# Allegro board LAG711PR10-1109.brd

Outline 228.4 x 155.5 mm; copper layers: TOP, GND1, IN1, VCC, IN2, IN3, GND2, BOTTOM. Coordinates in mm from the lower left corner of the outline.

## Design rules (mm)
net group CB: nets CBN CBP
net group CLK_CNV_CTX_DRX_: nets CLK_CNV_CTX_DRX_N CLK_CNV_CTX_DRX_P
net group CLK_PCIE_2: nets CLK_PCIE_N2 CLK_PCIE_P2
net group CLK_PEG_0: nets CLK_PEG_N0 CLK_PEG_P0
net group CNV_CRX_DTX_0: nets CNV_CRX_DTX_N0 CNV_CRX_DTX_P0
net group CNV_CTX_DRX_0: nets CNV_CTX_DRX_N0 CNV_CTX_DRX_P0
net group CPU_DP1_1: nets CPU_DP1_N1 CPU_DP1_P1
net group CPU_DP1_3: nets CPU_DP1_N3 CPU_DP1_P3
net group DDR_RESET: nets DDR_DRAMRST# DDR_DRAMRST#_R
net group DIFFPAIR12: nets ICSP_CLK ICSP_DAT
net group DIFFPAIR15: nets NCT7718_DXN NCT7718_DXP
net group EDP_AUX: nets EDP_AUXN EDP_AUXP
net group EDP_TX0: nets EDP_TXN0 EDP_TXP0
net group EDP_TX1: nets EDP_TXN1 EDP_TXP1
net group HDMI_L_CLK: nets HDMI_L_CLKN HDMI_L_CLKP
net group HDMI_L_TX_1: nets HDMI_L_TX_N1 HDMI_L_TX_P1
net group HDMI_TX_0: nets HDMI_TX_N0 HDMI_TX_P0
net group HDMI_TX_2: nets HDMI_TX_N2 HDMI_TX_P2
net group LAN_MDI0: nets LAN_MDIN0 LAN_MDIP0
net group LAN_MDI2: nets LAN_MDIN2 LAN_MDIP2
net group M_CLKA1: nets M_CLKA1 M_CLKA#1
net group M_WCKA#1: nets M_WCKA0_0 M_WCKA#0_0
net group M_WCKA#2: nets M_WCKA1_0 M_WCKA#1_0
net group PCIE_CRX_DTX_10: nets PCIE_CRX_DTX_N10 PCIE_CRX_DTX_P10
net group PCIE_CRX_DTX_14: nets PCIE_CRX_DTX_N14 PCIE_CRX_DTX_P14
net group PCIE_CRX_DTX_16: nets PCIE_CRX_DTX_N16 PCIE_CRX_DTX_P16
net group PCIE_CTX_C_DRX_10: nets PCIE_CTX_C_DRX_N10 PCIE_CTX_C_DRX_P10
net group PCIE_CTX_C_DRX_14: nets PCIE_CTX_C_DRX_N14 PCIE_CTX_C_DRX_P14
net group PCIE_CTX_C_DRX_16: nets PCIE_CTX_C_DRX_N16 PCIE_CTX_C_DRX_P16
net group PCIE_CTX_DRX_10: nets PCIE_CTX_DRX_N10 PCIE_CTX_DRX_P10
net group PCIE_CTX_DRX_14: nets PCIE_CTX_DRX_N14 PCIE_CTX_DRX_P14
net group PCIE_CTX_DRX_16: nets PCIE_CTX_DRX_N16 PCIE_CTX_DRX_P16
net group PCIE_RCOMP: nets PCIE_RCOMPN PCIE_RCOMPP
net group PEG_CRX_C_GTX_6: nets PEG_CRX_C_GTX_N6 PEG_CRX_C_GTX_P6
net group PEG_CRX_C_GTX_8: nets PEG_CRX_C_GTX_N8 PEG_CRX_C_GTX_P8
net group PEG_CRX_GTX_6: nets PEG_CRX_GTX_N6 PEG_CRX_GTX_P6
net group PEG_CRX_GTX_8: nets PEG_CRX_GTX_N8 PEG_CRX_GTX_P8
net group PEG_CTX_C_GRX_5: nets PEG_CTX_C_GRX_N5 PEG_CTX_C_GRX_P5
net group PEG_CTX_C_GRX_6: nets PEG_CTX_C_GRX_N6 PEG_CTX_C_GRX_P6
net group PEG_CTX_C_GRX_7: nets PEG_CTX_C_GRX_N7 PEG_CTX_C_GRX_P7
net group PEG_CTX_C_GRX_8: nets PEG_CTX_C_GRX_N8 PEG_CTX_C_GRX_P8
net group PEG_CTX_GRX_6: nets PEG_CTX_GRX_N6 PEG_CTX_GRX_P6
net group PEG_CTX_GRX_8: nets PEG_CTX_GRX_N8 PEG_CTX_GRX_P8
net group RJ45_MDI1: nets RJ45_MDIN1 RJ45_MDIP1
net group RJ45_MDI3: nets RJ45_MDIN3 RJ45_MDIP3
net group SATA_CRX_C_DTX_0: nets SATA_CRX_C_DTX_N0 SATA_CRX_C_DTX_P0
net group SATA_CRX_DTX_0: nets SATA_CRX_DTX_N0 SATA_CRX_DTX_P0
net group SATA_CTX_C_DRX_0: nets SATA_CTX_C_DRX_N0 SATA_CTX_C_DRX_P0
net group SATA_CTX_DRX_0: nets SATA_CTX_DRX_N0 SATA_CTX_DRX_P0
net group USB3_1_MRX_DTX_4: nets USB3_1_MRX_DTX_N4 USB3_1_MRX_DTX_P4
net group USB3_1_MTX_DRX_4: nets USB3_1_MTX_DRX_N4 USB3_1_MTX_DRX_P4
net group USB3_2_MTX_C_DRX_4: nets USB3_2_MTX_C_DRX_N4 USB3_2_MTX_C_DRX_P4
net group USB3_CRX_C_MTX_4: nets USB3_CRX_C_MTX_N4 USB3_CRX_C_MTX_P4
net group USB3_CRX_L_DTX_1: nets USB3_CRX_L_DTX_N1 USB3_CRX_L_DTX_P1
net group USB3_CTX_C_DRX_1: nets USB3_CTX_C_DRX_N1 USB3_CTX_C_DRX_P1
net group USB3_CTX_C_MRX_4: nets USB3_CTX_C_MRX_N4 USB3_CTX_C_MRX_P4
net group USB3_CTX_L_DRX_1: nets USB3_CTX_L_DRX_N1 USB3_CTX_L_DRX_P1
net group USB20_1_R: nets USB20_N1_R USB20_P1_R
net group USB20_2_R: nets USB20_N2_R USB20_P2_R
net group USB20_3_R: nets USB20_N3_R USB20_P3_R
net group USB20_4_R: nets USB20_N4_R USB20_P4_R
net group USB20_4_RR: nets USB20_N4_RR USB20_P4_RR
net group USB20_6: nets USB20_N6 USB20_P6
net group USB20_7: nets USB20_N7 USB20_P7
net group USB20_8: nets USB20_N8 USB20_P8
net group VRAM_ABI: nets M_ABIA0 M_ABIA1
net group VRAM_CLK: nets M_CLKA0 M_CLKA#0
net group 15: nets CLK_TP_SIO XTALIN XTALOUT
net group 20: nets LANXIN LANXIN_R LANXOUT LANXOUT_R XCLK_BIASREF XTAL24_IN XTAL24_IN_R XTAL24_OUT XTAL24_OUT_R
net group ASYNCHRONOUS: nets CATERR# H_PECI H_PROCHOT# H_PROCHOT#_R H_THERMTRIP# H_VCCST_PWRGD PECI_EC SCLK_CPU SDIO_CPU VCCST_PWRGD XDP_BPM#0 XDP_BPM#1 XDP_BPM#2 XDP_BPM#3
net group AUDIO: nets AUD_HP1_JACK_L AUD_HP1_JACK_L1 AUD_HP1_JACK_R AUD_HP1_JACK_R1 CPVEE HPOUT_L HPOUT_R LINE1-L_C LINE1-L_R LINE1_L LINE1_R RING2 RING2_R SLEEVE SLEEVE_R
net group CLK_S: nets MEC_XTAL1 MEC_XTAL1_R MEC_XTAL2 REFCLK_CNV REFCLK_CNV_R SUSCLK SUSCLK_EC SUSCLK_WLAN
net group CLKREQ: nets CLKREQ_PCIE#1 CLKREQ_PCIE#1_R CLKREQ_PCIE#2 CLKREQ_PCIE#2_R CLKREQ_PCIE#4 CLKREQ_PEG#0 CLKREQ_PEG#0_R
net group CNV: nets CLK_CNV_CRX_DTX_N CLK_CNV_CRX_DTX_P CNV_CRX_DTX_N1 CNV_CRX_DTX_P1 CNV_CTX_DRX_N1 CNV_CTX_DRX_P1
net group CNV_S: nets CNV_BRI_CRX_DTX CNV_BRI_CRX_DTX_R CNV_BRI_CTX_DRX CNV_BRI_CTX_DRX_R CNV_RGI_CRX_DTX CNV_RGI_CRX_DTX_R CNV_RGI_CTX_DRX CNV_RGI_CTX_DRX_R
net group DDR-COMP: nets SM_RCOMP0 SM_RCOMP1 SM_RCOMP2
net group DDRA_CLK: nets DDR_A_CLK0 DDR_A_CLK1 DDR_A_CLK#0 DDR_A_CLK#1
net group DDRA_CMD: nets DDR_A_ACT# DDR_A_ALERT# DDR_A_BA0 DDR_A_BA1 DDR_A_BG0 DDR_A_BG1 DDR_A_CAS# DDR_A_MA0 DDR_A_MA1 DDR_A_MA2 DDR_A_MA3 DDR_A_MA4 DDR_A_MA5 DDR_A_MA6 DDR_A_MA7 DDR_A_MA8 DDR_A_MA9 DDR_A_MA10 DDR_A_MA11 DDR_A_MA12 DDR_A_MA13 DDR_A_PAR DDR_A_RAS# DDR_A_WE#
net group DDRA_CTL: nets DDR_A_CKE0 DDR_A_CKE1 DDR_A_CKE2 DDR_A_CKE3 DDR_A_CS#0 DDR_A_CS#1 DDR_A_ODT0 DDR_A_ODT1
net group DDRA_D0: nets DDR_A_D0 DDR_A_D1 DDR_A_D2 DDR_A_D3 DDR_A_D4 DDR_A_D5 DDR_A_D6 DDR_A_D7
net group DDRA_D1: nets DDR_A_D8 DDR_A_D9 DDR_A_D10 DDR_A_D11 DDR_A_D12 DDR_A_D13 DDR_A_D14 DDR_A_D15
net group DDRA_D2: nets DDR_A_D16 DDR_A_D17 DDR_A_D18 DDR_A_D19 DDR_A_D20 DDR_A_D21 DDR_A_D22 DDR_A_D23
net group DDRA_D3: nets DDR_A_D24 DDR_A_D25 DDR_A_D26 DDR_A_D27 DDR_A_D28 DDR_A_D29 DDR_A_D30 DDR_A_D31
net group DDRA_D4: nets DDR_A_D32 DDR_A_D33 DDR_A_D34 DDR_A_D35 DDR_A_D36 DDR_A_D37 DDR_A_D38 DDR_A_D39
net group DDRA_D5: nets DDR_A_D40 DDR_A_D41 DDR_A_D42 DDR_A_D43 DDR_A_D44 DDR_A_D45 DDR_A_D46 DDR_A_D47
net group DDRA_D6: nets DDR_A_D48 DDR_A_D49 DDR_A_D50 DDR_A_D51 DDR_A_D52 DDR_A_D53 DDR_A_D54 DDR_A_D55
net group DDRA_D7: nets DDR_A_D56 DDR_A_D57 DDR_A_D58 DDR_A_D59 DDR_A_D60 DDR_A_D61 DDR_A_D62 DDR_A_D63
net group DDRA_DQS: nets DDR_A_DQS0 DDR_A_DQS1 DDR_A_DQS2 DDR_A_DQS3 DDR_A_DQS4 DDR_A_DQS5 DDR_A_DQS6 DDR_A_DQS7 DDR_A_DQS#0 DDR_A_DQS#1 DDR_A_DQS#2 DDR_A_DQS#3 DDR_A_DQS#4 DDR_A_DQS#5 DDR_A_DQS#6 DDR_A_DQS#7
net group DDRB_CLK: nets DDR_B_CLK0 DDR_B_CLK1 DDR_B_CLK#0 DDR_B_CLK#1
net group DDRB_CMD: nets DDR_B_ACT# DDR_B_ALERT# DDR_B_BA0 DDR_B_BA1 DDR_B_BG0 DDR_B_BG1 DDR_B_CAS# DDR_B_MA0 DDR_B_MA1 DDR_B_MA2 DDR_B_MA3 DDR_B_MA4 DDR_B_MA5 DDR_B_MA6 DDR_B_MA7 DDR_B_MA8 DDR_B_MA9 DDR_B_MA10 DDR_B_MA11 DDR_B_MA12 DDR_B_MA13 DDR_B_PAR DDR_B_RAS# DDR_B_WE#
net group DDRB_CTL: nets DDR_B_CKE0 DDR_B_CKE1 DDR_B_CKE2 DDR_B_CKE3 DDR_B_CS#0 DDR_B_CS#1 DDR_B_ODT0 DDR_B_ODT1
net group DDRB_D0: nets DDR_B_D0 DDR_B_D1 DDR_B_D2 DDR_B_D3 DDR_B_D4 DDR_B_D5 DDR_B_D6 DDR_B_D7
net group DDRB_D1: nets DDR_B_D8 DDR_B_D9 DDR_B_D10 DDR_B_D11 DDR_B_D12 DDR_B_D13 DDR_B_D14 DDR_B_D15
net group DDRB_D2: nets DDR_B_D16 DDR_B_D17 DDR_B_D18 DDR_B_D19 DDR_B_D20 DDR_B_D21 DDR_B_D22 DDR_B_D23
net group DDRB_D3: nets DDR_B_D24 DDR_B_D25 DDR_B_D26 DDR_B_D27 DDR_B_D28 DDR_B_D29 DDR_B_D30 DDR_B_D31
net group DDRB_D4: nets DDR_B_D32 DDR_B_D33 DDR_B_D34 DDR_B_D35 DDR_B_D36 DDR_B_D37 DDR_B_D38 DDR_B_D39
net group DDRB_D5: nets DDR_B_D40 DDR_B_D41 DDR_B_D42 DDR_B_D43 DDR_B_D44 DDR_B_D45 DDR_B_D46 DDR_B_D47
net group DDRB_D6: nets DDR_B_D48 DDR_B_D49 DDR_B_D50 DDR_B_D51 DDR_B_D52 DDR_B_D53 DDR_B_D54 DDR_B_D55
net group DDRB_D7: nets DDR_B_D56 DDR_B_D57 DDR_B_D58 DDR_B_D59 DDR_B_D60 DDR_B_D61 DDR_B_D62 DDR_B_D63
net group DDRB_DQS: nets DDR_B_DQS0 DDR_B_DQS1 DDR_B_DQS2 DDR_B_DQS3 DDR_B_DQS4 DDR_B_DQS5 DDR_B_DQS6 DDR_B_DQS7 DDR_B_DQS#0 DDR_B_DQS#1 DDR_B_DQS#2 DDR_B_DQS#3 DDR_B_DQS#4 DDR_B_DQS#5 DDR_B_DQS#6 DDR_B_DQS#7
net group DP: nets CPU_DP2_AUXN CPU_DP2_AUXP CPU_DP2_N0 CPU_DP2_N1 CPU_DP2_P0 CPU_DP2_P1
net group EDP: nets EDP_AUXN_C EDP_AUXP_C EDP_TXN0_C EDP_TXN1_C EDP_TXP0_C EDP_TXP1_C
net group EDP-COMP: nets EDP_COMP
net group ESPI: nets ESPI_CLK ESPI_CLK_R ESPI_CS# ESPI_IO0 ESPI_IO0_R ESPI_IO1 ESPI_IO1_R ESPI_IO2 ESPI_IO2_R ESPI_IO3 ESPI_IO3_R ESPI_RST#
net group HDA: nets DMIC_CLK DMIC_CLK_EDP DMIC_DATA DMIC_DATA_EDP HDA_BIT_CLK HDA_BIT_CLK_R HDA_SDIN0 HDA_SDIN0_R HDA_SDOUT HDA_SDOUT_R HDA_SYNC HDA_SYNC_R
net group HDMI: nets CPU_DP1_N0 CPU_DP1_N2 CPU_DP1_P0 CPU_DP1_P2 HDMI_CLKN HDMI_CLKP HDMI_L_TX_N0 HDMI_L_TX_N2 HDMI_L_TX_P0 HDMI_L_TX_P2 HDMI_TX_N1 HDMI_TX_P1
net group HDMI_DDC: nets CPU_DP1_CTRL_CLK CPU_DP1_CTRL_DATA HDMI_CTRL_CLK HDMI_CTRL_DAT
net group I2C_SCL: nets I2C_0_SCL I2C_0_SCL_R I2C_1_SCL I2C_3_SCL
net group I2C_SDA: nets DAT_TP_SIO I2C_0_SDA I2C_0_SDA_R I2C_1_SDA I2C_3_SDA
net group KB: nets KSI0 KSI1 KSI2 KSI3 KSI4 KSI5 KSI6 KSI7 KSO0 KSO1 KSO2 KSO3 KSO4 KSO5 KSO6 KSO7 KSO8 KSO9 KSO10 KSO11 KSO12 KSO13 KSO14 KSO15 KSO16
net group LAN: nets LAN_MDIN1 LAN_MDIN3 LAN_MDIP1 LAN_MDIP3 RJ45_MDIN0 RJ45_MDIN2 RJ45_MDIP0 RJ45_MDIP2
net group PCIE: nets PCIE_CRX_C_DTX_N9 PCIE_CRX_C_DTX_P9 PCIE_CRX_DTX_N9 PCIE_CRX_DTX_N13 PCIE_CRX_DTX_N15 PCIE_CRX_DTX_P9 PCIE_CRX_DTX_P13 PCIE_CRX_DTX_P15 PCIE_CTX_C_DRX_N9 PCIE_CTX_C_DRX_N13 PCIE_CTX_C_DRX_N15 PCIE_CTX_C_DRX_P9 PCIE_CTX_C_DRX_P13 PCIE_CTX_C_DRX_P15 PCIE_CTX_DRX_N9 PCIE_CTX_DRX_N13 PCIE_CTX_DRX_N15 PCIE_CTX_DRX_P9 PCIE_CTX_DRX_P13 PCIE_CTX_DRX_P15
net group PEG: nets PEG_CRX_C_GTX_N5 PEG_CRX_C_GTX_N7 PEG_CRX_C_GTX_P5 PEG_CRX_C_GTX_P7 PEG_CRX_GTX_N5 PEG_CRX_GTX_N7 PEG_CRX_GTX_P5 PEG_CRX_GTX_P7 PEG_CTX_GRX_N5 PEG_CTX_GRX_N7 PEG_CTX_GRX_P5 PEG_CTX_GRX_P7
net group PLAT_CLK: nets CLK_ITPXDP_N CLK_ITPXDP_P CLK_PCIE_N1 CLK_PCIE_N4 CLK_PCIE_P1 CLK_PCIE_P4
net group RTC: nets PCH_RTCRST# PCH_RTCX1 PCH_RTCX2
net group SATA: nets SATA_CRX_C_DTX_N1 SATA_CRX_C_DTX_P1 SATA_CRX_DTX_N1 SATA_CRX_DTX_P1 SATA_CTX_C_DRX_N1 SATA_CTX_C_DRX_P1 SATA_CTX_DRX_N1 SATA_CTX_DRX_P1
net group SMBUS: nets CLK_SMB DAT_SMB MEM_SMBCLK MEM_SMBDATA PBAT_CHG_SMBCLK PBAT_CHG_SMBDAT PCH_SMBCLK PCH_SMBDATA SML0_SMBCLK SML0_SMBDATA SML1_SMBCLK SML1_SMBDATA THM_SML1_CLK THM_SML1_DATA VGA_SMB_CK3 VGA_SMB_DA3
net group SPI: nets CPU_SPI_0_CLK CPU_SPI_0_CS#0 CPU_SPI_0_CS#2 CPU_SPI_0_D0 CPU_SPI_0_D1 CPU_SPI_0_D2 CPU_SPI_0_D3 CPU_SPI_CLK CPU_SPI_D0 CPU_SPI_D1 CPU_SPI_D2 CPU_SPI_D3 SPI_CLK_ROM SPI_CLK_ROM2 SPI_CLK_TPM SPI_D0_ROM SPI_D0_ROM2 SPI_D0_TPM SPI_D1_ROM SPI_D1_ROM2 SPI_D1_TPM SPI_D2_ROM SPI_D2_ROM2 SPI_D3_ROM SPI_D3_ROM2
net group SPK: nets AUD_SPK_L+ AUD_SPK_L+_C AUD_SPK_L- AUD_SPK_L-_C AUD_SPK_R+ AUD_SPK_R+_C AUD_SPK_R- AUD_SPK_R-_C
net group SVID: nets ALERT#_CPU VIDALERT# VIDALERT_N VIDSCLK VIDSOUT
net group USB20: nets USB20_N1 USB20_N2 USB20_N3 USB20_N4 USB20_N5 USB20_N6_R USB20_N7_R USB20_N8_R USB20_N8_RR USB20_N10 USB20_P1 USB20_P2 USB20_P3 USB20_P4 USB20_P5 USB20_P6_R USB20_P7_R USB20_P8_R USB20_P8_RR USB20_P10
net group USB30: nets USB3_1_MTX_C_DRX_N4 USB3_1_MTX_C_DRX_P4 USB3_2_MRX_DTX_N4 USB3_2_MRX_DTX_P4 USB3_2_MTX_DRX_N4 USB3_2_MTX_DRX_P4 USB3_CRX_DTX_N1 USB3_CRX_DTX_N2 USB3_CRX_DTX_P1 USB3_CRX_DTX_P2 USB3_CRX_L_DTX_N2 USB3_CRX_L_DTX_P2 USB3_CRX_MTX_N4 USB3_CRX_MTX_P4 USB3_CTX_C_DRX_N2 USB3_CTX_C_DRX_P2 USB3_CTX_DRX_N1 USB3_CTX_DRX_N2 USB3_CTX_DRX_P1 USB3_CTX_DRX_P2 USB3_CTX_L_DRX_N2 USB3_CTX_L_DRX_P2 USB3_CTX_MRX_N4 USB3_CTX_MRX_P4
net group VRAM_ADD: nets M_MAA0_0 M_MAA0_1 M_MAA0_2 M_MAA0_3 M_MAA0_4 M_MAA0_5 M_MAA0_6 M_MAA0_7 M_MAA0_8 M_MAA1_0 M_MAA1_1 M_MAA1_2 M_MAA1_3 M_MAA1_4 M_MAA1_5 M_MAA1_6 M_MAA1_7 M_MAA1_8
net group VRAM_CTL: nets M_CASA#0 M_CASA#1 M_CKEA0 M_CKEA1 M_CSA#0 M_CSA#1 M_RASA#0 M_RASA#1 M_WEA#0 M_WEA#1
net group VRAM_D0: nets M_DA0 M_DA1 M_DA2 M_DA3 M_DA4 M_DA5 M_DA6 M_DA7
net group VRAM_D1: nets M_DA8 M_DA9 M_DA10 M_DA11 M_DA12 M_DA13 M_DA14 M_DA15
net group VRAM_D2: nets M_DA16 M_DA17 M_DA18 M_DA19 M_DA20 M_DA21 M_DA22 M_DA23
net group VRAM_D3: nets M_DA24 M_DA25 M_DA26 M_DA27 M_DA28 M_DA29 M_DA30 M_DA31
net group VRAM_D4: nets M_DA32 M_DA33 M_DA34 M_DA35 M_DA36 M_DA37 M_DA38 M_DA39
net group VRAM_D5: nets M_DA40 M_DA41 M_DA42 M_DA43 M_DA44 M_DA45 M_DA46 M_DA47
net group VRAM_D6: nets M_DA48 M_DA49 M_DA50 M_DA51 M_DA52 M_DA53 M_DA54 M_DA55
net group VRAM_D7: nets M_DA56 M_DA57 M_DA58 M_DA59 M_DA60 M_DA61 M_DA62 M_DA63
net group VRAM_DBI: nets M_DBIA0 M_DBIA1 M_DBIA2 M_DBIA3 M_DBIA4 M_DBIA5 M_DBIA6 M_DBIA7
net group VRAM_EDC: nets M_EDCA0 M_EDCA1 M_EDCA2 M_EDCA3 M_EDCA4 M_EDCA5 M_EDCA6 M_EDCA7
net group VRAM_WCK: nets M_WCKA0_1 M_WCKA1_1 M_WCKA#0_1 M_WCKA#1_1
net group XDP: nets CFG0 CFG1 CFG2 CFG3 CFG4 CFG5 CFG6 CFG7 CFG8 CFG9 CFG10 CFG11 CFG12 CFG13 CFG14 CFG15 CFG16 CFG17 CFG18 CFG19 CPU_XDP_TCK0 PCH_DPWROK PCH_JTAG_TCK1 PCH_RSMRST#_Q SOC_XDP_TDI SOC_XDP_TDO SOC_XDP_TMS SOC_XDP_TRST# XDP_HOOK0 XDP_HOOK3 XDP_ITP_PMODE XDP_PRDY# XDP_PREQ# XDP_PRSENT_CPU
nets with their own width: min track width 0.152; nets VCCSENSE VSSSENSE
nets with their own width: min track width 0.254; nets +3.3V_SPI +3VALW_PCH +LAN_VDD33 +RTC_CELL CFG_RCOMP CNV_WT_RCOMP EMMC_RCOMP HDMI_PLL_GND KB_BL_CTRL# KB_LED_DET_C MCT0 MCT1 MCT2 MCT3 N17389450
nets with their own width: min track width 0.305; nets +5V_KB_BL CPU_POPIRCOMP VDD10
nets with their own width: min track width 0.381; nets +1.8V_AVDD +1.8V_CPVDD +3V_DVDD +5V_AVDD +17.4V_BATT+
nets with their own width: min track width 0.508; nets +1.2V_DDR +1.2VP +1.8VALW_EC +1.8VALWP +2.5VP +3VALW +3VALW_DSW +3VALW_EC +3VALWP +3VLP +3VS +3VS_CAM +3VS_SSD +5VS +FP_VCC +RTC_CELL_VBAT +RTC_PWR +RTC_SOC +RTC_VCC +TP_VDD +VCC_CORE +VCC_GT +VCC_SA +VCCLDOSRAM_1P24 +VCCPLL_OC +VCCST +VGA_CORE AUD_AGND BST_VCORE1 EC_AGND GND LOM_TCT N19964609 PHASE_VCORE1 VCCDPHY_1P24
nets with their own width: min track width 1.016; nets +0.6V_DDR_VTT +1.8V_PRIM +2.5V_MEM +5V_HDD VDDREG
nets with their own width: min track width 1.524; nets +0.6VSP +5V_HDMI +DCBAT_LCD
nets with their own width: min track width 2.032; nets +3.3V_WLAN +5V_PVDD +5VALW +LCDVDD +LCDVDD_LCD +USB3_VCC
nets with their own width: min track width 3.048; nets +CCG_VBUS
nets with their own width: min track width 3.81; nets +19VB

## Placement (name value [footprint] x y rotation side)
C1  0.47U_0402_6.3V6K  [C_0402]  63.86 31.3 180 top
C2  22P_0402_50V8J  [C_0402]  60.69 35.11 180 top
C3  1U_0201_6.3V6M  [C_0201]  64.33 37.78 180 top
C4  0.1U_0402_16V7K  [C_0402]  216.25 29.51 90 top
C5  0.1U_0402_50V7K  [C_0402]  214.28 59.43 0 top
C6  1000P_0402_50V7K  [C_0402]  214.27 60.57 0 top
C7  0.1U_0402_16V7K  [C_0402]  212.77 57.72 180 top
C8  1U 6.3V M X5R 0201  [C_0201]  212.72 56.83 180 top
C9  82P_0402_50V8J  [C_0402]  212.77 55.94 180 top
C12  0.1U_0402_16V7K  [C_0402]  215.25 52.13 180 top
C13  0.1U_0402_16V7K  [C_0402]  215.25 51.24 180 top
C14  0.1U_0402_16V7K  [C_0402]  215.25 50.22 180 top
C15  0.1U_0402_16V7K  [C_0402]  215.25 49.33 180 top
C16  1U_0201_6.3V6M  [C_0201]  221.26 58.22 0 top
C17  0.1U_0402_16V7K  [C_0402]  215.25 53.14 180 top
C18  10P_0402_50V8J  [C_0402]  211.62 42.68 270 top
C19  0.1U_0402_16V7K  [C_0402]  215.25 54.03 180 top
C21  1U_0402_10V6K  [C_0402]  16.87 131.76 180 bottom
C22  .1U_0402_16V7K  [C_0402]  96.94 34.91 90 bottom
C23  .1U_0402_16V7K  [C_0402]  106.21 29.09 270 bottom
C24  10P_0402_50V8J  [C_0402]  127.53 28.99 0 top
C25  10P_0402_50V8J  [C_0402]  127.53 28.1 0 top
C26  0.1U_0402_16V7K  [C_0402]  111.92 28.08 270 bottom
C27  22U_0603_6.3V6M  [C_0603]  184.02 70.11 90 top
C28  0.1U_0402_16V7K  [C_0402]  182.46 61.98 315 bottom
C29  470P_0603_50V8J  [C_0603]  88.81 118.74 270 bottom
C30  2200P_0402_25V7K  [C_0402]  181.84 61.22 225 bottom
C31  0.1U_0402_16V7K  [C_0402]  130.46 44.59 270 top
C32  100P_0402_50V8J  [C_0402]  129.57 44.59 270 top
C33  0.1U_0402_10V7K  [C_0402]  60.69 32.57 180 top
C35  1U_0201_6V3M  [C_0201]  212.75 33.69 270 top
C36  0.1U_0402_10V7K  [C_0402]  211.88 45.56 90 top
C37  1U_0201_6V3M  [C_0201]  213.95 38.43 180 top
C39  1U_0201_6V3M  [C_0201]  212.76 47.21 180 top
CA1  .1U_0402_16V7K  [C_0402]  27.8 18.92 180 top
CA2  10U_0603_10V6M  [C_0603]  28.04 17.84 180 top
CA3  10U_0402_6.3V6M  [C_0402]  28.1 7.74 0 top
CA4  10U_0603_10V6M  [C_0603]  33.43 7.23 270 top
CA5  .1U_0402_16V7K  [C_0402]  34.51 7.25 270 top
CA6  10U_0603_10V6M  [C_0603]  32.23 7.23 270 top
CA7  .1U_0402_16V7K  [C_0402]  31.15 7.25 270 top
CA8  10P_0402_50V8J  [C_0402]  38.5 10.41 0 top
CA9  6.8P_0402_50V  [C_0402]  38.5 11.3 0 top
CA10  10U_0402_6.3V6M  [C_0402]  26.7 9.77 90 top
CA11  .1U_0402_16V7K  [C_0402]  27.78 11.18 270 top
CA12  10U_0402_6.3V6M  [C_0402]  38.53 14.35 180 top
CA13  .1U_0402_16V7K  [C_0402]  35.78 14.52 90 top
CA14  10U_0402_6.3V6M  [C_0402]  37.82 9.33 0 top
CA15  .1U_0402_16V7K  [C_0402]  37.58 15.3 180 top
CA16  2.2U_0402_6.3V6M  [C_0402]  26.69 14.85 180 top
CA17  1U_0603_16V7  [C_0603]  25.5 9.77 90 top
CA18  1U_0603_16V7  [C_0603]  24.29 11.17 270 top
CA19  10U_0402_6.3V6M  [C_0402]  26.07 15.81 0 top
CA20  33P_0402_50V8J  [C_0402]  39.42 12.19 180 top
CA21  10U_0402_6.3V6M  [C_0402]  28.1 8.95 0 top
CA22  10U_0402_6.3V6M  [C_0402]  38.46 13.14 180 top
CA23  10U_0402_6.3V6M  [C_0402]  31.85 17.71 90 top
CA24  .1U_0402_16V7K  [C_0402]  33.83 18.85 180 top
CA25  0.1U_0402_10V7K  [C_0402]  25.69 19.99 90 top
CA28  1000P_0402_50V7K  [C_0402]  26.4 5.58 180 top
CA29  1000P_0402_50V7K  [C_0402]  23.48 2.73 180 top
CA30  1000P_0402_50V7K  [C_0402]  21.24 1.76 90 top
CA31  1000P_0402_50V7K  [C_0402]  26.39 4.45 270 top
CA32  0.1U_0402_16V7K  [C_0402]  34.65 17.14 180 top
CA33  10U_0603_10V6M  [C_0603]  29.18 17.71 90 top
CA34  10U_0603_10V6M  [C_0603]  30.39 17.71 90 top
CA35  100P_0402_50V8J  [C_0402]  17.18 10.3 270 bottom
CA36  100P_0402_50V8J  [C_0402]  18.07 11.98 90 bottom
CA37  680P_0402_50V8J  [C_0402]  22.59 16.7 180 top
CA38  680P_0402_50V8J  [C_0402]  19.52 16.7 0 top
CA39  680P_0402_50V8J  [C_0402]  22.59 15.81 180 top
CA40  680P_0402_50V8J  [C_0402]  19.52 15.81 0 top
CC1  0.1U_0402_16V7K  [C_0402]  105.7 109.46 90 top
CC2  100P_0402_50V8J  [C_0402]  106.97 109.46 90 top
CC3  10P_0402_50V8J  [C_0402]  104 53.14 180 top
CC4  0.1U_0402_10V7K  [C_0402]  119.36 37.4 180 bottom
CC5  33P_0402_50V8J  [C_0402]  119.11 36.06 180 bottom
CC6  2.2P_0201_25V8C  [C_0201]  111.58 61.27 180 bottom
CC7  1U_0201_6.3V6M  [C_0201]  102.45 58.29 0 top
CC8  1U_0201_6.3V6M  [C_0201]  105.9 58.29 180 top
CC9  15P_0201_25V8J  [C_0201]  142.66 47.15 270 bottom
CC10  15P_0201_25V8J  [C_0201]  142.66 48.09 90 bottom
CC11  6.8P_0402_50V8C  [C_0402]  105.14 46.21 0 top
CC12  6.8P_0402_50V8C  [C_0402]  104.28 46.21 180 top
CC13  0.1U_0402_10V7K  [C_0402]  98.89 58.48 0 top
CC14  1U_0201_6.3V6M  [C_0201]  93.84 56.83 180 top
CC15  1U_0201_6.3V6M  [C_0201]  131.61 59.15 270 top
CC16  0.1U_0201_6.3V6K  [C_0201]  130.37 61.02 180 top
CC17  1U_0201_6.3V6M  [C_0201]  104.59 63.69 180 top
CC18  1U_0201_6.3V6M  [C_0201]  130.06 60.32 180 top
CC19  1U_0201_6.3V6M  [C_0201]  138.9 66.1 0 bottom
CC20  10U_0402_6.3V6M  [C_0402]  119.92 75.14 90 top
CC21  10U_0402_6.3V6M  [C_0402]  147.1 37.73 270 top
CC22  10U_0402_6.3V6M  [C_0402]  123.15 63.56 0 top
CC23  10U_0402_6.3V6M  [C_0402]  146.08 37.73 270 top
CC24  10U_0402_6.3V6M  [C_0402]  120.81 75.14 90 top
CC25  10U_0402_6.3V6M  [C_0402]  126.96 60.78 0 top
CC26  1U_0201_6.3V6M  [C_0201]  122.91 75.01 90 top
CC27  1U_0201_6.3V6M  [C_0201]  120.78 63.79 270 top
CC28  1U_0201_6.3V6M  [C_0201]  122.34 75.01 90 top
CC29  1U_0201_6.3V6M  [C_0201]  120.44 74.44 270 top
CC30  1U_0201_6.3V6M  [C_0201]  121.35 63.79 270 top
CC31  1U_0201_6.3V6M  [C_0201]  123.48 75.01 90 top
CC32  1U_0201_6.3V6M  [C_0201]  123.12 64.32 0 top
CC33  1U_0201_6.3V6M  [C_0201]  121.07 74.44 270 top
CC34  22U_0603_6.3V6M  [C_0603]  100.49 82.16 90 top
CC35  10U_0402_6.3V6M  [C_0402]  99.09 82.28 90 top
CC36  10U_0402_6.3V6M  [C_0402]  100.62 65.4 270 top
CC37  10U_0402_6.3V6M  [C_0402]  97.7 82.28 90 top
CC38  10U_0402_6.3V6M  [C_0402]  102.02 65.4 270 top
CC39  10U_0402_6.3V6M  [C_0402]  99.22 65.4 270 top
CC40  10U_0402_6.3V6M  [C_0402]  102.02 82.28 90 top
CC41  1U_0201_6.3V6M  [C_0201]  116.43 70.07 270 top
CC42  1U_0201_6.3V6M  [C_0201]  116.43 85.63 270 top
CC43  1U_0201_6.3V6M  [C_0201]  116.43 73.17 90 top
CC44  1U_0201_6.3V6M  [C_0201]  116.43 77.38 270 top
CC45  10U_0402_6.3V6M  [C_0402]  104.3 82.28 90 top
CC46  10U_0402_6.3V6M  [C_0402]  103.41 65.4 270 top
CC47  10U_0402_6.3V6M  [C_0402]  103.16 82.28 90 top
CC48  1U_0402_6.3V6K  [C_0402]  125.22 60.83 0 top
CC49  22U_0603_6.3V6M  [C_0603]  129.99 56.68 270 top
CC50  1U_0201_6.3V6M  [C_0201]  121.74 60.79 180 top
CC51  0.1U_0402_10V7K  [C_0402]  122.75 61.51 180 top
CC52  1U_0201_6.3V6M  [C_0201]  122.59 60.28 270 top
CC53  1U_0402_6.3V6K  [C_0402]  144.42 59.75 0 top
CC54  47U_0603_6.3V6M  [C_0603]  144.43 60.89 0 top
CC55  1U_0201_6.3V6M  [C_0201]  125.89 57.04 90 top
CC56  1U_0402_6.3V6K  [C_0402]  133.21 46.41 180 top
CC57  47U_0603_6.3V6M  [C_0603]  133.7 47.56 180 top
CC58  4.7U_0402_6.3V6M  [C_0402]  121.57 48.5 90 top
CC59  1U_0201_6.3V6M  [C_0201]  121.4 57.97 270 top
CC60  1U_0201_6.3V6M  [C_0201]  124.04 60.12 180 top
CC61  1U_0201_6.3V6M  [C_0201]  124.75 54.38 90 top
CC62  1U_0201_6.3V6M  [C_0201]  125.18 59.43 90 top
CC63  1U_0201_6.3V6M  [C_0201]  122.61 58.66 180 top
CC64  1U_0201_6.3V6M  [C_0201]  125.84 47.94 180 top
CC65  1U_0201_6.3V6M  [C_0201]  119.63 48.45 0 top
CC66  0.1U_0201_6.3V6K  [C_0201]  119.63 47.87 0 top
CC67  0.1U_0402_16V7K  [C_0402]  98.03 41.84 180 top
CC68  1U_0402_6.3V6K  [C_0402]  95.87 48.45 180 top
CC69  100P_0402_50V8J  [C_0402]  92.83 43.43 270 top
CC70  0.1U_0402_16V7K  [C_0402]  98.03 45.52 180 top
CC71  100P_0402_50V8J  [C_0402]  141.39 64.94 90 bottom
CC72  22U_0603_6.3V6M  [C_0603]  146.47 63.56 90 top
CC74  0.1U_0402_10V7K  [C_0402]  130.72 27.06 270 bottom
CC75  0.1U_0402_10V7K  [C_0402]  93.48 54.68 270 top
CC76  0.1U_0402_10V7K  [C_0402]  132.06 110.08 180 bottom
CC77  0.1U_0402_10V7K  [C_0402]  89.06 40.44 0 top
CC78  0.1U_0402_10V7K  [C_0402]  93.73 42.53 90 top
CC79  0.1U_0402_10V7K  [C_0402]  131.66 42.05 270 bottom
CD1  1U_0201_6.3V6M  [C_0201]  79.66 44.85 90 top
CD2  10U_0402_6.3V6M  [C_0402]  78.65 44.45 90 top
CD3  1U_0201_6.3V6M  [C_0201]  73.19 43.96 90 top
CD4  1U_0201_6.3V6M  [C_0201]  72.55 43.96 90 top
CD5  10U_0402_6.3V6M  [C_0402]  74.01 43.73 90 top
CD6  0.1U_0402_16V7K~D  [C_0402]  77 43.8 90 top
CD7  2.2U_0402_6.3V6M  [C_0402]  75.98 43.8 90 top
CD8  1U_0201_6.3V6M  [C_0201]  81.15 67.5 0 top
CD9  1U_0201_6.3V6M  [C_0201]  80.51 90.74 0 top
CD10  1U_0201_6.3V6M  [C_0201]  67.94 69.65 0 top
CD11  1U_0201_6.3V6M  [C_0201]  80.51 69.65 0 top
CD12  1U_0201_6.3V6M  [C_0201]  69.29 63.05 180 top
CD13  1U_0201_6.3V6M  [C_0201]  79.83 47.56 180 top
CD14  1U_0201_6.3V6M  [C_0201]  70.82 52.73 0 top
CD15  1U_0201_6.3V6M  [C_0201]  77.03 58.22 180 top
CD16  10U_0402_6.3V6M  [C_0402]  67.53 72.19 180 top
CD17  10U_0402_6.3V6M  [C_0402]  71.48 96.71 180 top
CD18  10U_0402_6.3V6M  [C_0402]  79.87 102.04 180 top
CD19  10U_0402_6.3V6M  [C_0402]  70.46 78.15 0 top
CD20  10U_0402_6.3V6M  [C_0402]  79.47 81.59 180 top
CD21  10U_0402_6.3V6M  [C_0402]  79.47 79.94 180 top
CD22  10U_0402_6.3V6M  [C_0402]  79.47 78.29 180 top
CD23  10U_0402_6.3V6M  [C_0402]  70.2 73.97 0 top
CD24  330U_D2_2V_Y  [C_D2]  89.47 72.19 180 top
CD25  0.1U_0402_16V7K~D  [C_0402]  71.7 65.57 180 top
CD26  S CER CAP 10P 50V J NPO 0201  [C_0201]  67.66 82.89 90 top
CD27  0.022U_0402_25V7K  [C_0402]  70.78 63.67 0 top
CD28  1U_0201_6.3V6M  [C_0201]  67.98 44.43 90 top
CD29  10U_0402_6.3V6M  [C_0402]  66.96 44.32 90 top
CD30  1U_0201_6.3V6M  [C_0201]  60.42 44.41 90 top
CD31  1U_0201_6.3V6M  [C_0201]  60.99 44.41 90 top
CD32  10U_0402_6.3V6M  [C_0402]  59.47 43.94 90 top
CD33  0.1U_0402_16V7K~D  [C_0402]  63.53 44.31 90 top
CD34  2.2U_0402_6.3V6M  [C_0402]  64.55 44.31 90 top
CD35  1U_0201_6.3V6M  [C_0201]  58.49 63.94 180 top
CD36  1U_0201_6.3V6M  [C_0201]  68.96 85.02 0 top
CD37  1U_0201_6.3V6M  [C_0201]  68.45 91.12 0 top
CD38  1U_0201_6.3V6M  [C_0201]  66.76 102.09 180 top
CD39  1U_0201_6.3V6M  [C_0201]  56.89 86.29 0 top
CD40  1U_0201_6.3V6M  [C_0201]  66.62 74.73 180 top
CD41  1U_0201_6.3V6M  [C_0201]  66.49 47.56 180 top
CD42  1U_0201_6.3V6M  [C_0201]  66.95 58.46 180 top
CD43  10U_0402_6.3V6M  [C_0402]  58.66 53.4 180 top
CD44  10U_0402_6.3V6M  [C_0402]  58.01 75.88 0 top
CD45  10U_0402_6.3V6M  [C_0402]  57.88 79.94 0 top
CD46  10U_0402_6.3V6M  [C_0402]  69.63 106.99 0 top
CD47  10U_0402_6.3V6M  [C_0402]  57.9 106.85 270 top
CD48  10U_0402_6.3V6M  [C_0402]  58.9 96.71 180 top
CD49  10U_0402_6.3V6M  [C_0402]  66.79 70.49 180 top
CD50  10U_0402_6.3V6M  [C_0402]  66.7 76.67 180 top
CD51  0.1U_0402_16V7K~D  [C_0402]  59.04 69.72 180 top
CD52  0.022U_0402_25V7K  [C_0402]  58.12 66.1 0 top
CE1  10U_0402_6.3V6M  [C_0402]  53.44 84.51 0 top
CE2  0.1U_0402_10V7K  [C_0402]  38.53 65.84 180 top
CE3  1000P_0402_50V7K  [C_0402]  33.24 73.83 90 top
CE4  1000P_0402_50V7K  [C_0402]  45.63 64.5 90 top
CE5  0.1U_0402_10V7K  [C_0402]  42.96 86.09 90 top
CE6  0.1U_0402_10V7K  [C_0402]  53.51 73.52 0 top
CE7  0.1U_0402_10V7K  [C_0402]  33.23 79.81 180 top
CE8  0.1U_0402_10V7K  [C_0402]  53.42 83.37 0 top
CE9  0.1U_0402_10V7K  [C_0402]  53.42 82.48 0 top
CE10  0.1U_0402_10V7K  [C_0402]  32.55 86.32 90 top
CE11  0.1U_0402_10V7K  [C_0402]  35.79 90.18 180 top
CE12  0.1U_0402_10V7K  [C_0402]  32.08 71.92 180 top
CE13  0.1U_0402_10V7K  [C_0402]  53.93 78.16 0 top
CE14  2.2U_0402_6.3V6M  [C_0402]  33.14 66.11 270 top
CE15  0.1U_0402_10V7K  [C_0402]  35.47 85.96 90 top
CE16  0.047U_0402_16V4Z  [C_0402]  51.74 86.26 90 top
CE17  0.1U_0402_10V7K  [C_0402]  44.74 65.41 270 top
CE18  100P_0402_50V8J  [C_0402]  50.07 65.41 270 top
CE19  0.1U_0402_10V7K  [C_0402]  47.53 65.41 270 top
CE20  33P_0402_50V8J  [C_0402]  54.85 79.05 180 top
CE21  0.1U_0402_10V7K  [C_0402]  32.34 91.11 270 top
CE22  0.1U_0402_10V7K  [C_0402]  40.98 90.48 0 top
CE23  1U_0402_16V6K  [C_0402]  43.85 65.41 270 top
CE24  47P_0402_50V8J  [C_0402]  40.98 89.21 0 top
CE25  12P_0402_50V8J  [C_0402]  32.2 69.82 90 top
CE26  2200P_0402_25V7K  [C_0402]  30.2 76.27 270 top
CE27  12P_0402_50V8J  [C_0402]  32.2 68.95 270 top
CE28  220P_0402_50V8J  [C_0402]  53.52 71.8 0 top
CE30  1000P_0402_50V7K  [C_0402]  49.9 86.26 90 top
CE31  2200P_0402_25V7K  [C_0402]  32.11 75.37 180 top
CE32  100P_0402_50V8J  [C_0402]  35.67 66.25 180 top
CI1  0.1U_0402_10V7K  [C_0402]  20.08 94.66 180 top
CI2  0.1U_0402_10V7K  [C_0402]  20.08 93.7 180 top
CI3  0.1U_0402_10V7K  [C_0402]  20.08 96.69 180 top
CI4  0.1U_0402_10V7K  [C_0402]  20.08 95.74 180 top
CI5  0.1U_0402_10V7K  [C_0402]  20.08 92.62 180 top
CI6  0.1U_0402_10V7K  [C_0402]  20.08 91.67 180 top
CI7  0.1U_0402_10V7K  [C_0402]  20.08 90.72 180 top
CI8  0.1U_0402_10V7K  [C_0402]  20.08 89.77 180 top
CI9  0.1U_0402_10V7K  [C_0402]  14.7 101.33 90 top
CL1  12P_0402_50V8J  [C_0402]  19.95 83.14 180 top
CL2  0.1U_0402_10V7K  [C_0402]  20.4 85.85 90 top
CL3  0.1U_0402_10V7K  [C_0402]  26.22 78.84 90 bottom
CL4  0.1U_0402_10V7K  [C_0402]  23.66 84.84 270 bottom
CL5  0.1U_0402_10V7K  [C_0402]  21.55 81.97 0 bottom
CL6  0.1U_0402_10V7K  [C_0402]  21.55 81.08 0 bottom
CL7  12P_0402_50V8J  [C_0402]  19.13 81.49 270 top
CL8  0.1U_0402_10V7K  [C_0402]  26.66 86.71 270 top
CL9  0.1U_0402_10V7K  [C_0402]  25.71 86.71 270 top
CL10  0.1U_0402_10V7K  [C_0402]  28.86 80.45 270 top
CL11  0.1U_0402_10V7K  [C_0402]  21.93 79.05 0 bottom
CL12  0.1U_0402_10V7K  [C_0402]  21.55 83.88 0 bottom
CL13  0.1U_0402_10V7K  [C_0402]  29.73 81.5 180 top
CL14  0.1U_0402_10V7K  [C_0402]  29.73 82.39 180 top
CL15  4.7U_0402_6.3V6M  [C_0402]  21.93 80.07 0 bottom
CL16  1U_0201_6V3M  [C_0201]  23.66 86.29 90 top
CL17  4.7U_0402_6.3V6M  [C_0402]  29.88 79.89 270 top
CL18  0.1U_0402_10V7K  [C_0402]  24.76 78.84 90 bottom
CL19  1U_0201_6.3V6M  [C_0201]  15.95 86.67 180 top
CL20  33P 2KV J NPO 1206 H1  [C_1206]  21.18 76.32 0 bottom
CL21  0.01U_0402_16V7K  [C_0402]  28.1 70.28 90 bottom
CLRP1  SHORT PADS  [SHORTPADS]  102.9 59.43 0 top
CLRP2  SHORT PADS  [SHORTPADS]  105.44 59.43 180 top
CO1  1000P_0402_50V7K  [C_0402]  192.96 65.72 180 top
CO2  0.1U_0402_10V7K  [C_0402]  192.96 66.73 180 top
CO3  10U_0603_10V6M  [C_0603]  193.33 64.57 180 top
CO4  0.01U_0402_16V7K  [C_0402]  186.22 62.49 270 bottom
CO5  0.01U_0402_16V7K  [C_0402]  187.23 62.49 270 bottom
CO6  0.01U_0402_16V7K  [C_0402]  189.26 62.49 270 bottom
CO7  0.01U_0402_16V7K  [C_0402]  190.28 62.49 270 bottom
CS1  10U_0603_10V6M  [C_0603]  23.15 26.6 180 top
CS3  0.1U_0402_10V7K  [C_0402]  27.83 26.73 0 top
CS4  1000P_0402_50V7K  [C_0402]  27.83 25.84 0 top
CS5  22U_0603_6.3V6M  [C_0603]  23.15 27.81 180 top
CS7  0.22U_0402_16V7K  [C_0402]  36.62 36.95 270 bottom
CS8  0.22U_0402_16V7K  [C_0402]  35.73 36.95 270 bottom
CS9  0.22U_0402_16V7K  [C_0402]  34.08 36.95 270 bottom
CS10  0.22U_0402_16V7K  [C_0402]  33.19 36.95 270 bottom
CS11  0.22U_0402_16V7K  [C_0402]  31.03 36.95 270 bottom
CS12  0.22U_0402_16V7K  [C_0402]  30.14 36.95 270 bottom
CS13  0.22U_0402_16V7K  [C_0402]  27.98 36.95 270 bottom
CS14  0.22U_0402_16V7K  [C_0402]  27.09 36.95 270 bottom
CS15  0.01U_0402_16V7K  [C_0402]  178.86 31.33 0 bottom
CS16  0.01U_0402_16V7K  [C_0402]  178.86 32.22 0 bottom
CS17  0.01U_0402_16V7K  [C_0402]  178.88 33.18 0 bottom
CS18  0.01U_0402_16V7K  [C_0402]  178.88 34.07 0 bottom
CS29  1000P_0402_50V7K  [C_0402]  183.63 36.25 180 bottom
CS30  0.1U_0402_10V7K  [C_0402]  183.63 37.14 180 bottom
CS31  10U_0603_10V6M  [C_0603]  183.49 35.87 180 top
CS32  0.1U_0402_10V7K  [C_0402]  170.71 31.68 0 top
CS33  10U_0603_10V6M  [C_0603]  170.6 32.76 0 top
CT1  47U_0603_6.3V6M  [C_0603]  31.85 113.81 270 bottom
CT2  0.1U_0402_10V7K  [C_0402]  26.78 121.6 180 top
CT3  0.1U_0402_10V7K  [C_0402]  26.78 122.49 180 top
CT4  0.1U_0402_10V7K  [C_0402]  26.78 123.5 180 top
CT5  0.1U_0402_10V7K  [C_0402]  26.78 124.39 180 top
CT6  0.1U_0402_10V7K  [C_0402]  17.7 125.09 180 top
CT7  0.1U_0402_10V7K  [C_0402]  17.7 124.2 180 top
CT8  0.1U_0402_10V7K  [C_0402]  17.7 123.31 180 top
CT9  0.1U_0402_10V7K  [C_0402]  17.89 116.64 180 top
CT10  0.1U_0402_10V7K  [C_0402]  17.89 117.53 180 top
CT11  4.7U_0402_6.3V6M  [C_0402]  17.7 126.04 180 top
CT12  10U_0603_25V6M  [C_0603]  10.38 120.52 0 bottom
CT13  10U_0603_10V6M  [C_0603]  30.32 113.91 270 bottom
CT14  22U_0603_6.3V6M  [C_0603]  33.63 113.81 270 bottom
CT15  0.47U_0402_50V6K  [C_0402]  10.5 122.49 0 bottom
CT16  0.47U_0402_50V6K  [C_0402]  10.5 121.6 0 bottom
CT17  0.47U_0402_50V6K  [C_0402]  10.37 119.82 0 top
CT18  0.47U_0402_50V6K  [C_0402]  10.37 122.61 0 top
CT20  0.1U_0402_10V7K  [C_0402]  27.97 114.56 270 bottom
CU1  0.1U_0402_10V7K  [C_0402]  25.54 59.8 180 top
CU2  0.1U_0402_10V7K  [C_0402]  25.54 58.78 180 top
CU4  4.7U_0402_6.3V  [C_0402]  19.01 59.62 0 bottom
CU5  22U_0603_6.3V6M  [C_0603]  19 56.45 0 bottom
CU6  22U_0603_6.3V6M  [C_0603]  19 58.22 0 bottom
CU7  100U_A_6.3VM_R70M  [C_A]  18.41 54.41 0 bottom
CU9  4.7U_0402_6.3V  [C_0402]  21.04 38.92 0 top
CU10  22U_0603_6.3V6M  [C_0603]  21.92 36.63 0 top
CU11  22U_0603_6.3V6M  [C_0603]  19.85 35.43 270 top
CU12  100U_A_6.3VM_R70M  [C_A]  21.71 34.73 0 top
CU13  1U_0201_6V3M  [C_0201]  19.17 49.08 0 bottom
CU14  0.1U_0402_10V7K  [C_0402]  24.01 33.13 180 top
CU15  0.1U_0402_10V7K  [C_0402]  24.01 32.23 180 top
CU16  1U_0201_6V3M  [C_0201]  205.67 34.98 90 top
CU17  22U_0603_6.3V6M  [C_0603]  202.45 36.57 45 top
CV1  0.22U_0201_6.3V6M  [C_0201]  113.28 147.9 270 bottom
CV2  0.22U_0201_6.3V6M  [C_0201]  113.91 147.9 270 bottom
CV3  0.22U_0201_6.3V6M  [C_0201]  114.68 147.9 270 bottom
CV4  0.22U_0201_6.3V6M  [C_0201]  115.31 147.9 270 bottom
CV5  0.22U_0201_6.3V6M  [C_0201]  116.62 142.34 270 top
CV6  0.22U_0201_6.3V6M  [C_0201]  115.99 142.34 270 top
CV7  0.22U_0201_6.3V6M  [C_0201]  118.27 143.61 270 top
CV8  0.22U_0201_6.3V6M  [C_0201]  118.91 143.61 270 top
CV9  0.22U_0201_6.3V6M  [C_0201]  115.96 146.3 90 bottom
CV10  0.22U_0201_6.3V6M  [C_0201]  116.59 146.3 90 bottom
CV11  0.22U_0201_6.3V6M  [C_0201]  117.36 146.3 90 bottom
CV12  0.22U_0201_6.3V6M  [C_0201]  117.99 146.3 90 bottom
CV13  0.22U_0201_6.3V6M  [C_0201]  118.75 146.3 90 bottom
CV14  0.22U_0201_6.3V6M  [C_0201]  119.39 146.3 90 bottom
CV15  0.22U_0201_6.3V6M  [C_0201]  120.15 146.3 90 bottom
CV16  0.22U_0201_6.3V6M  [C_0201]  120.79 146.3 90 bottom
CV17  8.2P 50V D NPO 0402  [C_0402]  109.64 143.11 90 bottom
CV18  8.2P 50V D NPO 0402  [C_0402]  109.64 140.47 270 bottom
CV20  1U_0201_6.3V6M  [C_0201]  117.6 132.9 0 top
CV26  1U_0201_6.3V6M  [C_0201]  115.73 131.02 90 top
CV27  10U_0402_6.3V6M  [C_0402]  112.9 130.56 180 top
CV28  0.68U_0402_10V  [C_0402]  117.48 135.17 270 top
CV29  0.68U_0402_10V  [C_0402]  116.67 136.16 180 top
CV30  0.082U_0402_16V  [C_0402]  114.78 133.91 90 top
CV31  0.68U_0402_10V  [C_0402]  114.91 137.97 90 top
CV32  0.1U_0402_10V6K  [C_0402]  59.85 124.09 270 top
CV33  1U_0201_6.3V6M  [C_0201]  117.45 130.02 270 top
CV34  0.1U_0201_6.3V6K  [C_0201]  116.75 130.02 270 top
CV40  10U_0402_6.3V6M  [C_0402]  128.25 136.2 180 top
CV41  2.2U_0402_6.3V6M  [C_0402]  128 137.98 180 top
CV42  2.2U_0402_6.3V6M  [C_0402]  128.25 137.09 180 top
CV43  2.2U_0402_6.3V6M  [C_0402]  128.33 129.94 180 top
CV44  2.2U_0402_6.3V6M  [C_0402]  128.79 127.25 90 top
CV45  2.2U_0402_6.3V6M  [C_0402]  128.33 129.05 180 top
CV46  0.1U_0201_6.3V6K  [C_0201]  127.73 138.73 90 top
CV47  0.01U_0402_16V7K  [C_0402]  128.33 130.83 180 top
CV49  10U_0402_6.3V6M  [C_0402]  113.76 141.04 270 top
CV50  1U_0201_6.3V6M  [C_0201]  113 140.94 270 top
CV54  10U_0402_6.3V6M  [C_0402]  125.83 141.54 180 top
CV55  1U_0201_6.3V6M  [C_0201]  125.76 138.34 270 top
CV56  1U_0201_6.3V6M  [C_0201]  126.34 138.34 270 top
CV57  1U_0201_6.3V6M  [C_0201]  125 139.21 90 top
CV58  1U_0201_6.3V6M  [C_0201]  124.43 139.21 90 top
CV59  1U_0201_6.3V6M  [C_0201]  123.86 139.21 90 top
CV60  1U_0201_6.3V6M  [C_0201]  123.29 139.21 90 top
CV61  10U_0402_6.3V6M  [C_0402]  122.78 143 90 top
CV62  1U_0201_6.3V6M  [C_0201]  125.15 137.16 0 top
CV63  1U_0201_6.3V6M  [C_0201]  123.22 137.13 270 top
CV64  1U_0201_6.3V6M  [C_0201]  119.29 136.33 180 top
CV65  1U_0201_6.3V6M  [C_0201]  118.91 134.64 90 top
CV67  10U_0402_6.3V6M  [C_0402]  121.08 134.62 180 top
CV68  10U_0402_6.3V6M  [C_0402]  119.16 129.93 270 top
CV69  10U_0402_6.3V6M  [C_0402]  120.56 129.93 270 top
CV70  10U_0402_6.3V6M  [C_0402]  120.86 131.03 0 top
CV71  10U_0402_6.3V6M  [C_0402]  121.41 131.94 0 top
CV72  10U_0402_6.3V6M  [C_0402]  125.05 129.22 180 top
CV73  2.2U_0402_6.3V6M  [C_0402]  122.34 132.84 0 top
CV74  2.2U_0402_6.3V6M  [C_0402]  122.34 133.73 0 top
CV75  2.2U_0402_6.3V6M  [C_0402]  122.36 135.77 0 top
CV76  2.2U_0402_6.3V6M  [C_0402]  125.09 134.89 180 top
CV77  2.2U_0402_6.3V6M  [C_0402]  127.94 133.1 180 top
CV78  2.2U_0402_6.3V6M  [C_0402]  124.34 131.99 90 top
CV81  10U_0402_6.3V6M  [C_0402]  127.11 125.53 180 top
CV82  10U_0402_6.3V6M  [C_0402]  127.11 126.42 180 top
CV83  1U_0201_6.3V6M  [C_0201]  127.86 125.32 270 top
CV84  10U_0402_6.3V6M  [C_0402]  131.11 123.06 180 top
CV85  1U_0201_6.3V6M  [C_0201]  131.07 123.88 180 top
CV86  10U_0402_6.3V6M  [C_0402]  121.5 136.96 0 top
CV87  10U_0402_6.3V6M  [C_0402]  125.09 135.78 180 top
CV88  1U_0201_6.3V6M  [C_0201]  124.93 130.88 180 top
CV89  1U_0201_6.3V6M  [C_0201]  123.61 132.1 180 top
CV90  1U_0201_6.3V6M  [C_0201]  120.98 135.38 180 top
CV91  10U_0402_6.3V6M  [C_0402]  133.18 121.47 0 top
CV92  1U_0201_6.3V6M  [C_0201]  131.95 123.5 0 top
CV93  0.1U_0201_6.3V6K  [C_0201]  131.95 124.14 0 top
CV94  1U_0201_6.3V6M  [C_0201]  129.71 146.43 180 bottom
CV95  1U_0201_6.3V6M  [C_0201]  134.64 148.2 0 bottom
CV96  120P_0402_50V8J  [C_0402]  150.94 115.73 90 bottom
CV97  68P_0402_50V8J  [C_0402]  147.64 116.58 270 bottom
CV98  0.1U_0402_16V4Z  [C_0402]  129.76 120.89 90 top
CV99  0.1U_0402_16V4Z  [C_0402]  127.36 122.93 0 top
CV100  2.2U_0402_6.3V6M  [C_0402]  128.02 133.99 180 top
CV101  2.2U_0402_6.3V6M  [C_0402]  128.25 135.31 180 top
CV102  2.2U_0402_6.3V6M  [C_0402]  122.39 128.84 0 top
CV103  2.2U_0402_6.3V6M  [C_0402]  126.13 131.96 90 top
CV104  2.2U_0402_6.3V6M  [C_0402]  122.36 134.88 0 top
CV105  2.2U_0402_6.3V6M  [C_0402]  125.05 130.13 180 top
CV106  2.2U_0402_6.3V6M  [C_0402]  126.56 127.94 90 top
CV107  2.2U_0402_6.3V6M  [C_0402]  122.35 130.02 0 top
CV108  2.2U_0402_6.3V6M  [C_0402]  125.23 131.95 90 top
CV109  2.2U_0402_6.3V6M  [C_0402]  126.09 134.87 90 top
CV120  0.1U_0201_6.3V6K  [C_0201]  125.21 134.15 270 top
CV121  0.1U_0201_6.3V6K  [C_0201]  125.83 134.16 270 top
CV150  1U_0201_6.3V6M  [C_0201]  163.98 144.39 0 top
CV151  1U_0201_6.3V6M  [C_0201]  154.64 149.09 0 bottom
CV152  10U_0402_6.3V6M  [C_0402]  162.34 140.58 180 top
CV153  1U_0201_6.3V6M  [C_0201]  164.27 139.57 0 bottom
CV154  1U_0201_6.3V6M  [C_0201]  156.79 135.12 180 top
CV155  1U_0201_6.3V6M  [C_0201]  164.27 140.71 0 bottom
CV156  1U_0201_6.3V6M  [C_0201]  157.6 135.12 0 top
CV157  1U_0201_6.3V6M  [C_0201]  164.3 137.22 0 bottom
CV158  1U_0201_6.3V6M  [C_0201]  164.3 136.2 0 bottom
CV159  1U_0201_6.3V6M  [C_0201]  159.38 135.12 0 top
CV160  1U_0201_6.3V6M  [C_0201]  164.27 138.49 0 bottom
CV161  0.1U_0201_10V6K  [C_0201]  164.36 126.86 0 bottom
CV162  0.1U_0201_10V6K  [C_0201]  164.36 127.94 0 bottom
CV163  0.1U_0201_10V6K  [C_0201]  164.06 137.21 0 top
CV164  0.1U_0201_10V6K  [C_0201]  164.35 118.68 0 bottom
CV165  0.1U_0201_10V6K  [C_0201]  164.35 122.74 0 bottom
CV166  0.1U_0201_10V6K  [C_0201]  164.35 121.72 0 bottom
CV167  0.1U_0201_10V6K  [C_0201]  160.3 149.33 90 top
CV168  0.1U_0201_10V6K  [C_0201]  159.34 149.32 90 top
CV169  0.1U_0201_10V6K  [C_0201]  157.43 149.32 90 top
CV170  0.1U_0201_10V6K  [C_0201]  164.36 124.7 0 bottom
CV171  1U_0201_6.3V6M  [C_0201]  161.11 125.41 180 top
CV172  1U_0201_6.3V6M  [C_0201]  156.11 132.01 90 bottom
CV173  10U_0402_6.3V6M  [C_0402]  161.2 132.33 0 bottom
CV174  1U_0201_6.3V6M  [C_0201]  149.67 116.64 0 top
CV175  1U_0201_6.3V6M  [C_0201]  152.88 128.43 270 top
CV176  1U_0201_6.3V6M  [C_0201]  153.6 129.66 0 top
CV177  1U_0201_6.3V6M  [C_0201]  157.16 130.74 0 top
CV178  1U_0201_6.3V6M  [C_0201]  164.21 130.11 0 bottom
CV179  1U_0201_6.3V6M  [C_0201]  164.36 125.79 0 top
CV180  1U_0201_6.3V6M  [C_0201]  152.6 129.66 180 top
CV181  1U_0201_6.3V6M  [C_0201]  164.21 130.11 0 top
CV182  0.1U_0201_10V6K  [C_0201]  164.36 124.7 0 top
CV183  0.1U_0201_10V6K  [C_0201]  164.36 126.86 0 top
CV184  0.1U_0201_10V6K  [C_0201]  164.36 127.94 0 top
CV185  0.1U_0201_10V6K  [C_0201]  164.36 129.02 0 top
CV186  0.1U_0201_10V6K  [C_0201]  164.35 120.71 0 bottom
CV187  0.1U_0201_10V6K  [C_0201]  164.35 119.69 0 bottom
CV188  0.1U_0201_10V6K  [C_0201]  164.35 122.74 0 top
CV189  0.1U_0201_10V6K  [C_0201]  164.35 121.72 0 top
CV190  0.1U_0201_10V6K  [C_0201]  164.35 120.71 0 top
CV191  0.1U_0201_10V6K  [C_0201]  164.35 119.69 0 top
CW1  10U_0402_6.3V6M  [C_0402]  69.12 117.09 270 top
CW2  0.1U_0402_10V7K  [C_0402]  70.27 117.1 270 top
CW3  0.1U_0402_10V7K  [C_0402]  69.2 137.22 180 top
CW4  10P_0402_50V8J  [C_0402]  69.2 138.23 180 top
CW5  0.1U_0402_10V7K  [C_0402]  73.12 116.82 90 bottom
CW6  0.1U_0402_10V7K  [C_0402]  72.23 116.82 90 bottom
CX1  0.1U_0402_10V7K  [C_0402]  91.64 30.61 0 top
CX2  10U_0402_6.3V6M  [C_0402]  91.64 31.5 0 top
CX3  0.1U_0402_10V7K  [C_0402]  92.35 36.22 180 top
CX4  10U_0402_6.3V6M  [C_0402]  92.35 37.13 180 top
CX5  0.1U_0402_10V7K  [C_0402]  80.67 35.4 270 top
CX6  0.1U_0402_10V7K  [C_0402]  82.45 35.36 270 top
CX7  10U_0402_6.3V6M  [C_0402]  81.56 35.36 270 top
CZ1  1U_0201_6V3M  [C_0201]  130.26 106.1 0 bottom
CZ2  1U_0201_6.3V6M  [C_0201]  128.63 109.15 180 bottom
CZ3  0.1U_0402_10V7K  [C_0402]  130.26 106.99 0 bottom
CZ4  0.1U_0402_10V7K  [C_0402]  130.26 105.09 0 bottom
CZ5  0.1U_0402_10V7K  [C_0402]  125.94 109.15 0 bottom
CZ6  1000P_0402_50V7K  [C_0402]  124.44 107.25 180 bottom
CZ7  1000P_0402_50V7K  [C_0402]  124.44 106.23 180 bottom
CZ8  0.1U_0402_10V7K  [C_0402]  125.81 104.33 0 bottom
CZ9  1U_0201_6.3V6M  [C_0201]  153.88 39.17 0 top
CZ10  1U_0201_6V3M  [C_0201]  153.88 40.19 0 top
CZ11  0.1U_0402_10V7K  [C_0402]  153.96 41.13 90 top
CZ12  0.1U_0402_10V7K  [C_0402]  149.56 38.03 0 top
CZ13  1U_0201_6V3M  [C_0201]  35.21 59.03 270 top
CZ14  1U_0201_6.3V6M  [C_0201]  37.31 55.88 0 top
CZ15  0.1U_0402_10V7K  [C_0402]  39.16 60.45 180 top
CZ16  470P_0402_50V7K  [C_0402]  44.08 58.36 270 top
CZ17  470P_0402_50V7K  [C_0402]  42.21 57.54 0 top
CZ18  0.1U_0402_10V7K  [C_0402]  40 55.88 180 top
CZ19  1U_0201_6.3V6M  [C_0201]  68.11 32.75 90 top
CZ20  0.1U_0402_10V7K  [C_0402]  71.08 31.17 0 top
CZ21  1U_0201_6V3M  [C_0201]  71.92 32.62 90 top
CZ22  1000P_0402_50V7K  [C_0402]  71.92 35.31 270 top
CZ23  0.1U_0402_10V7K  [C_0402]  72.87 38.36 270 top
CZ24  1U_0201_6.3V6M  [C_0201]  136.86 117.01 90 bottom
CZ25  0.1U_0402_16V7K  [C_0402]  137.71 115.95 180 bottom
CZ26  0.1U_0402_10V7K  [C_0402]  135.87 114.24 180 bottom
CZ27  0.1U_0402_10V7K  [C_0402]  131.36 117.34 180 bottom
CZ28  100P_0402_50V8J  [C_0402]  132.88 114.48 0 bottom
CZ29  1U_0201_6.3V6M  [C_0201]  121.7 109.69 90 bottom
CZ30  0.1U_0402_10V7K  [C_0402]  118.78 107.58 270 bottom
CZ31  1U_0201_6.3V6M  [C_0201]  115.92 109.72 90 bottom
CZ32  0.1U_0402_16V7K  [C_0402]  119.67 106.66 90 bottom
CZ33  0.1U_0402_16V7K  [C_0402]  117.89 106.66 90 bottom
CZ34  0.1U_0402_10V7K  [C_0402]  122.46 111.45 270 bottom
CZ35  330P_0402_50V7K  [C_0402]  119.54 113.93 270 bottom
CZ36  330P_0402_50V7K  [C_0402]  118.65 113.93 270 bottom
CZ37  0.1U_0402_10V7K  [C_0402]  116.68 111.51 270 bottom
CZ38  1U_0201_6.3V6M  [C_0201]  93.42 61.6 180 top
CZ39  1U_0201_6V3M  [C_0201]  93.42 60.71 180 top
CZ40  0.1U_0402_10V7K  [C_0402]  99.93 62.29 180 top
CZ41  0.1U_0201_6.3V6K  [C_0201]  36.29 57.48 180 top
D1  -  [BAS40C_SOT23-3]  65.31 30.44 180 top
D2  BAT54C_SOT23-3~D  [BAT54C_SOT23-3]  217.81 53.14 270 top
D3  -  [RB551V-30_SOD323-2]  213.32 40.43 180 top
D4  BAT54C_SOT23-3~D  [BAT54C_SOT23-3]  220.4 60.89 90 top
D5  -  [RB551V-30_SOD323-2]  116.3 33.9 0 bottom
D8  RB751S40T1G_SOD523-2  [RB520SM-30T2R_EMD2-2]  61.76 33.37 90 top
DA1  -  [L03ESDL5V0CC3-2_SOT23-3]  23.81 5.77 90 top
DA2  -  [L03ESDL5V0CC3-2_SOT23-3]  17.15 2.98 270 top
DA3  BAT54C_SOT23-3~D  [BAT54C_SOT23-3]  23.43 23.81 90 top
DA4  BAT54ATB_SOT-523-3  [BAT54ATB_SOT523-3]  20.14 12.25 90 top
DA5  AZ5123-02S.R7G_SOT23-3  [AZ5123-02SPR7G_SOT23-3]  21.05 20.47 180 top
DA6  -  [L03ESDL5V0CC3-2_SOT23-3]  17.11 7.91 0 top
DA7  -  [L03ESDL5V0CC3-2_SOT23-3]  17.11 19.32 180 top
DE1  AZ5125-01H.R7G_SOD523-2  [AZ5125-01HPR7G_SOD523-2]  36.61 86.91 270 top
DI1  -  [BAW56W_SOT323-3]  24.46 88.7 270 bottom
DW1  RB751S40T1G_SOD523-2  [RB520SM-30T2R_EMD2-2]  66.11 133.66 0 top
DW2  RB751S40T1G_SOD523-2  [RB520SM-30T2R_EMD2-2]  66.11 134.93 0 top
DZ1  -  [RB751S40T1G_SOD523-2]  108.28 52.26 0 bottom
DZ2  RB751S40T1G_SOD523-2  [RB520SM-30T2R_EMD2-2]  70.01 30.75 270 top
DZ4  -  [RB751S40T1G_SOD523-2]  97.53 49.59 180 top
DZ5  -  [RB751S40T1G_SOD523-2]  131.95 108.96 180 bottom
DZ6  -  [RB751S40T1G_SOD523-2]  156.12 40.36 90 top
DZ7  RB751S40T1G_SOD523-2  [RB520SM-30T2R_EMD2-2]  72.64 108.33 180 top
EC1  1000P_0402_50V7K  [C_0402]  219.11 65.13 90 top
EC2  0.1U_0402_10V7K  [C_0402]  223.35 63.43 0 top
ED1  -  [L03ESDL5V0CC3-2_SOT23-3]  223.07 66.1 90 top
ED2  -  [L03ESDL5V0CG3-2_SOT-523-3]  210.54 40.83 90 bottom
ED3  -  [L03ESDL5V0CG3-2_SOT-523-3]  216.63 44.38 270 top
ED4  -  [L03ESDL5V0CG3-2_SOT-523-3]  219.94 48.32 270 top
EU1  S DIO(BR) AZ1045-04F.R7G DFN2510P10E ESD  [L05ESDL5V0NA-4_SLP2510P8-10-9]  20.06 57.53 270 top
EU2  -  [AZC199-02SPR7G_SOT23-3]  21.2 54.86 90 top
EU3  S DIO(BR) AZ1045-04F.R7G DFN2510P10E ESD  [L05ESDL5V0NA-4_SLP2510P8-10-9]  19.14 30.81 270 top
EU4  -  [AZC199-02SPR7G_SOT23-3]  28.99 39.56 270 bottom
EU5  -  [L03ESDL5V0CG3-2_SOT-523-3]  220.63 35.18 180 bottom
EU6  -  [L03ESDL5V0CG3-2_SOT-523-3]  222.67 35.81 180 bottom
EU7  -  [L30ESD24VC3-2_SOT23-3]  13.27 117.91 270 bottom
EU8  S DIO(BR) AZ1045-04F.R7G DFN2510P10E ESD  [L05ESDL5V0NA-4_SLP2510P8-10-9]  13.57 126.03 90 top
EU9  S DIO(BR) AZ1045-04F.R7G DFN2510P10E ESD  [L05ESDL5V0NA-4_SLP2510P8-10-9]  13.57 118.91 90 top
EU10  -  [AZC199-02SPR7G_SOT23-3]  15.79 121.47 90 top
EU11  -  [AZC199-02SPR7G_SOT23-3]  13.39 125.15 270 bottom
F1  1.5A_24V_SMD1812P150TF-24  [F_SMD1812P150TF-24]  209.46 52.43 90 bottom
F3  0.5A_13.2V_MF-NSMF050-2  [F_MF-NSMF050-2]  99.37 35.49 0 bottom
FD1  FIDUCAL  [FIDUCIAL_C40M80]  13.5 131.25 0 top
FD2  FIDUCAL  [FIDUCIAL_C40M80]  222.67 26.16 0 top
FD3  FIDUCAL  [FIDUCIAL_C40M80]  36.23 131 180 bottom
FD4  FIDUCAL  [FIDUCIAL_C40M80]  225.4 55.81 180 bottom
FI1  1.5A_6V_1206L150PR~D  [F_1206L150PR]  16.29 101.34 270 top
H1  HOLEA  [H_3P0-G]  6.85 130.5 0 top
H3  HOLEA  [H_5P0]  169.05 109.5 0 top
H4  HOLEA  [H_3P0]  7.9 85.8 0 top
H5  HOLEA  [H_3P0-G]  8 41.2 0 top
H6  HOLEA  [H_3P0-G]  207.45 63.85 0 top
H7  HOLEA  [H_3P0-G]  141.55 27.1 0 top
H8  HOLEA  [H_3P3-G]  6.9 112.6 0 top
H9  HOLEA  [H_3P5]  142.95 117.18 180 bottom
H10  HOLEA  [H_3P5]  101.31 130.35 180 bottom
H11  HOLEA  [H_3P2-G]  126.01 153.05 180 bottom
H12  HOLEA  [H_3P2-G]  45.5 129.9 0 top
H13  HOLEA  [H_3P0X4P0]  213.85 65.5 90 top
H14  HOLEA  [H_5P6N]  19.1 111.3 90 top
HCPU1  HOLEA  [H_3P9]  113.08 100.81 0 top
HCPU2  HOLEA  [H_3P9]  137.38 100.78 0 top
HCPU3  HOLEA  [H_3P9]  113.08 39.81 0 top
HCPU4  HOLEA  [H_3P9]  137.38 39.81 0 top
JDB1  HRS_BM20B-20DS-0P4V  [HRS_BM20B-20DS-0P4V_20P-T]  145.63 37.8 270 bottom
JDEG1  JXT_FP241AH-010GAAM  [JXT_FP241AH-010GAAM_10P]  43.75 97.16 180 top
JDIMM1  DEREN_40-42271-26001RHF  [LOTES_ADDR0206-P001A02_260P]  79.15 109.99 90 bottom
JDIMM2  DEREN_40-42261-26001RHF  [LOTES_ADDR0205-P001A02_260P]  66.45 109.99 270 bottom
JEDP1  ACES_51540-04001-P01  [ACES_51540-04001-P01_40P]  212.37 60.45 270 bottom
JESPI1  JXT_FP241AH-010GAAM  [JXT_FP241AH-010GAAM_10P]  44.69 94.37 90 bottom
JFAN1  ACES_50224-00401-001  [ACES_50224-00401-001_4P]  181.48 70.7 90 bottom
JFP1  ACES_51522-00801-001  [ACES_51522-00801-001_8P]  221.02 30.77 180 bottom
JHDD1  ACES_51625-01201-001  [ACES_51625-01201-001_12P]  190.2 35.58 180 bottom
JHDMI1  CONCR_099AKAC19NBLCNF  [ACON_HMRF6-AK120C_19P-T]  11.05 92.35 90 bottom
JHP1  YUQIU_PJ753-F07J1BE-B  [YUQIU_PJ753-F07J1BE-B_7P-T]  12.65 7.9 90 bottom
JIOB1  ACES_51524-0160N-001  [ACES_51524-0160N-001_16P]  213.2 36.8 180 bottom
JKB1  HEFEN_AFB02-S30F1A-HF  [HEFEN_AFB02-S30F1A-HF_30P-T]  59.75 34.05 180 bottom
JKBBL1  ACES_51575-00401-001  [ACES_51575-00401-001_4P]  95.05 34.52 180 bottom
JLAN1  SANTA_130460-N  [SINGA_2RJ3076-078211F_8P-T]  12.95 77.72 90 bottom
JODD1  ACES_50673-0120N-P01  [ACES_50673-0120N-P01_12P]  185.2 64.3 180 bottom
JP1  PAD-OPEN1X1M  [JUMP_43X39]  124.32 109.02 180 bottom
JP2  PAD-OPEN1X1M  [JUMP_43X39]  124.32 104.45 180 bottom
JP3  -  [JUMP_43X79]  147.78 40.06 180 top
JP5  2MM  [JUMP_43X39]  15.6 85.15 180 top
JP8  -  [JUMP_43X79]  70.46 36.97 90 top
JP9  -  [JUMP_43X79]  131.23 114.91 180 bottom
JP10  -  [JUMP_43X79]  123.06 113.3 90 bottom
JP11  -  [JUMP_43X79]  115.1 113.3 90 bottom
JPWR1  JXT_FP226H-004S1AM  [JXT_FP226H-004S1AM_4P]  221.24 63.38 0 bottom
JSPK1  ACES_50224-00401-001  [ACES_50224-00401-001_4P]  16.42 5.88 180 bottom
JSSD1  LCN_DAN05-67306-0103  [LCN_DAN05-67306-0103_75P]  39.38 34.03 180 bottom
JTP1  ACES_51524-0080N-001  [ACES_51524-0080N-001_8P]  125.05 30.5 180 bottom
JUSB1  ACON_TARAN-9R1391  [ACON_TARAN-9R1391_9P]  15.88 56.65 90 bottom
JUSB2  ACON_TARAN-9R1391  [ACON_TARAN-9R1391_9P]  15.88 32.75 90 bottom
JUSBC1  JAE_DX07S024JJ2R1300~D  [JAE_DX07S024JJ2R1300_24P]  7.35 123.82 270 top
JVGA1  ACES_51625-01601-001  [ACES_51625-01601-001_16P-T]  217.65 38.75 90 top
JWLAN1  LOTES_APCI0136-P001A  [LOTES_APCI0136-P001A_75P]  79.02 120.65 90 bottom
L3  MCM1012B900F06BP_4P  [INPAQ_MCM1012B900F06BP_4P]  218.85 42.99 180 top
L4  MCM1012B900F06BP_4P  [INPAQ_MCM1012B900F06BP_4P-NPM]  204.89 39.94 0 bottom
LA1  BLM15PX330SN1D_2P  [MURAT_BLM15PX330SN1D_2P]  21.71 14.85 0 top
LA2  BLM15PX330SN1D_2P  [MURAT_BLM15PX330SN1D_2P]  22.68 12.89 180 top
LA3  BLM15PX330SN1D_2P  [MURAT_BLM15PX330SN1D_2P]  22.68 11.11 180 top
LA4  BLM15PX330SN1D_2P  [MURAT_BLM15PX330SN1D_2P]  18.47 14.85 0 top
LA5  BLM15PX221SN1D_2P  [MURAT_BLM15PX221SN1D_2P]  36.72 11.3 180 top
LED1  LTW-295DSKS-5A_YEL-WHITE~D  [LED_LTW-295DSKS-5A_4P]  3.25 133.05 270 bottom
LI1  HCM1012GH900BP_4P  [INPAQ_HCM1012GH900BP_4P-NPM]  16.15 94.4 0 top
LI2  HCM1012GH900BP_4P  [INPAQ_HCM1012GH900BP_4P-NPM]  16.15 96.43 0 top
LI3  HCM1012GH900BP_4P  [INPAQ_HCM1012GH900BP_4P-NPM]  16.15 90.46 0 top
LI4  HCM1012GH900BP_4P  [INPAQ_HCM1012GH900BP_4P-NPM]  16.15 92.43 0 top
LT1  MCM1012B900F06BP_4P  [INPAQ_MCM1012B900F06BP_4P]  16.93 119.82 0 top
LU1  MCM1012B900F06BP_4P  [INPAQ_MCM1012B900F06BP_4P]  25.57 55.68 0 top
LU2  HCM1012GH900BP_4P  [INPAQ_HCM1012GH900BP_4P-NPM]  22.3 59.54 0 top
LU3  HCM1012GH900BP_4P  [INPAQ_HCM1012GH900BP_4P-NPM]  22.3 57.7 0 top
LU4  MCM1012B900F06BP_4P  [INPAQ_MCM1012B900F06BP_4P]  31.06 39.54 0 bottom
LU5  HCM1012GH900BP_4P  [INPAQ_HCM1012GH900BP_4P-NPM]  20.7 32.94 0 top
LU6  HCM1012GH900BP_4P  [INPAQ_HCM1012GH900BP_4P-NPM]  20.83 30.92 0 top
LU7  MCM1012B900F06BP_4P  [INPAQ_MCM1012B900F06BP_4P]  210.77 34.69 270 top
LU8  MCM1012B900F06BP_4P  [INPAQ_MCM1012B900F06BP_4P]  207.94 36.01 90 top
LV2  BLM15BD121SN1D_0402  [R_0402]  110.38 133.15 0 top
LV6  BLM15BD221SN1D_2P  [MURAT_BLM15BB221SN1D_2P]  126.46 123.65 90 top
LV7  BLM15BD121SN1D_0402  [R_0402]  131.1 121.2 90 top
LV8  BLM15BD121SN1D_0402  [R_0402]  134.1 120.58 180 top
NOREF  -  []  113.08 39.81 0 top
NOREF#2  -  []  213.85 65.5 0 top
NOREF#3  -  []  6.9 112.6 0 top
NOREF#4  -  []  87.16 82.99 0 top
NOREF#5  -  []  85.84 62.14 0 top
NOREF#6  -  []  63.76 36.13 0 top
NOREF#7  -  []  8 41.2 0 top
NOREF#8  -  []  100.28 116.73 270 top
NOREF#9  -  []  36.39 123.34 0 top
NOREF#10  -  []  45.5 129.9 0 top
NOREF#11  -  []  35.59 118.25 0 top
NOREF#12  -  []  6.9 112.6 0 top
NOREF#13  -  []  126.01 153.05 0 top
NOREF#14  -  []  207.45 63.85 0 top
NOREF#15  -  []  137.38 100.81 0 top
